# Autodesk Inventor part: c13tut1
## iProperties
Shininess: 64.0
Angle Display Precision: 2
Document Length Units: 11269
Document Angle Units: 11279
Document Time Units: 11290
Document Mass Units: 11283
Document Length Units Precision: 3
Document Angle Units Precision: 2
Compacted: True
Created: 2002-04
Part Number: c13tut1
Document SubType Name: Modeling
Density: 1 g/cm^3
Density: 0.0
Volumn: 0.0
Area: 0.0
PropertySet Name: Model Information
Control State: 0
Master: False
Checked Out: False
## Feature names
1. Extrusion1
2. Fillet1
